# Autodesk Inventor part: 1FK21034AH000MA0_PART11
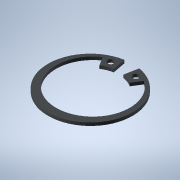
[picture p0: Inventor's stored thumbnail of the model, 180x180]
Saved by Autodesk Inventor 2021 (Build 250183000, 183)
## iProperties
Created: 2025-04
Part Number: 1FK21034AH000MA0_PART11
Material: Generic
Catalog Web Link: www.3dfindit.com
Description: -Servo synchronous motor
Document SubType Name: Modeling
Designer: psAdmin
Mass: 0.288797 g
Surface Area: 7.43416 cm^2
Volume: 0.288797 cm^3
Density: 1 g/cm^3
Appearance: PSOLRGB-212-217-219
Category: PARTsolutions
Title: 1FK21034AH000MA0_PART11
Author: Cadenas PARTsolutions
Comments: Servo synchronous motor
Sending System: PARTsolutions
Preprocessor: ST-DEVELOPER v19.3
PSOL_IDENT_0: {$CADENAS_DATA/23d-libs/siemens_ag/_cat_/ec/b7/1fk21034ah000ma0.prj},216 {VTYP=3D},{NB=1FK21034AH000
PSOL_IDENT_1: MA0_PART11},{LINA=1FK21034AH000MA0_PART11},{NN=1FK21034AH000MA0_PART11},{NOPRJ=TRUE},{DATE=19.08.202
PSOL_IDENT_2: 5 14:01:05},{GEOMDATE=30.07.2025 02:01:02},{VERSION=},{LINEID=10},{WBVAR=},{WBNUMERIC=}  {NB=1FK2103
PSOL_IDENT_3: 4AH000MA0_PART11},{LINA=1FK21034AH000MA0_PART11},{KT=DUMMY},{PREVIEW=../../../_pool_/7c/50/p_d211_xx
PSOL_IDENT_4: _00932j.png},{DESCSHORT=SIMOTICS S-1FK2 HD, SINAMICS S210 3AC 400V-480V, 1.01 Nm, 4500 rpm},{DESCLON
PSOL_IDENT_5: G=SIMOTICS S-1FK2 HD servo motor M0=1.27 Nm; PN = 0.48 kW at nN=4500 rpm (380-480 V); PN = 0.3 kW at
PSOL_IDENT_6: nN=2500 rpm (200-240 V); degree of protection IP64; cylindrical shaft D14 x 30 mm; absolute encoder
PSOL_IDENT_7: 22-bit + 12-bit multiturn (encoder AM22DQC); with OCC interface; plug size M17, rotatable; SIMOTICS
PSOL_IDENT_8: S-1FK2 servomotorfor a wide range of uses in industrial environments. SIMOTICS S‑1FK2 servomotors a
PSOL_IDENT_9: re compact synchronous motors with a high dynamic performance that set themselves apart as a result
PSOL_IDENT_10: of their high power density, degree of protection and overload capability. The motors are available
PSOL_IDENT_11: in two variants: as High Dynamic variant (highest dynamic performance as a result of the low intrins
PSOL_IDENT_12: ic moment of inertia for applications demanding a high dynamic performance with low moved masses) -
PSOL_IDENT_13: and as Compact variant (precise and stable closed-loop control for medium up to large moved masses a
PSOL_IDENT_14: s a result of a medium intrinsic moment of inertia). SIMOTICSS‑1FK2 servomotors fully exploit their
PSOL_IDENT_15: strengths in a system with the SINAMICSS210 frequency converter and simple connection using the one
PSOL_IDENT_16: cable connection (OCC). Advantages include the short control and positioning times, fast and precise
PSOL_IDENT_17: correction of disturbing quantities as well as stable control with a high dynamic performance. The
PSOL_IDENT_18: servo motors can be configured to address a wide range of requirements. For example with and without
PSOL_IDENT_19: holding brake, IP64 or IP65 degree of protection, singleturn or multiturn absolute encoders - to na
PSOL_IDENT_20: me just a few. Further, the servomotors are available in different shaft heights extending from 20 t
PSOL_IDENT_21: o 100. A shaft sealing ring is available to achieve an IP65 degree of protection and for subsequent
PSOL_IDENT_22: mounting at the motor or as spare part. SIMOTICS - the optimum motor for each and every motion contr
PSOL_IDENT_23: ol application.},{INTNO=4034106444822},{SUPPLIERALTNO=1FK2103-4AH00-0MA0},{MANUID=1FK21034AH000MA0},
PSOL_IDENT_24: {MANUNAME=Siemens},{MANUTYPEDESC=SYNCHRONOUS MOTOR 1FK2 HD 1,27 NM},{AAU732=SIMOTICS},{AAO057=S-1FK2
PSOL_IDENT_25: },{AAU734=SIMOTICS S-1FK2 HD servo motor M0=1.27 Nm; PN = 0.48 kW at nN=4500 rpm (380-480 V); PN = 0
PSOL_IDENT_26: .3 kW at nN=2500 rpm (200-240 V); degree of protection IP64; cylindrical shaft D14 x 30 mm; absolute
PSOL_IDENT_27: encoder 22-bit + 12-bit multiturn (encoder AM22DQC); with OCC interface; plug size M17, rotatable;}
PSOL_IDENT_28: ,{AAW338=SYNCHRONOUS MOTOR 1FK2 HD 1,27 NM},{AAO742=SIMOTICS},{AAO663=4034106444822},{NOCUPEROU=1},{
PSOL_IDENT_29: PRICEQUANTITY=1},{QUANTITYMIN=1},{QUANTITYINT=1},{CTN=85015100},{COO=RO},{AAO676=1FK2103-4AH00-0MA0}
PSOL_IDENT_30: ,{AAO677=Siemens AG},{ORDERUNIT=C62},{CONTENTUNIT=C62}
NB: 1FK21034AH000MA0_PART11
NT: Servo synchronous motor
NBSYN: $MANUID._PART11
LINA: 1FK21034AH000MA0_PART11
CATALOG: SIEMENS
PREVIEW: ../../../_pool_/7c/50/p_d211_xx_00932j.png
DESCSHORT: SIMOTICS S-1FK2 HD, SINAMICS S210 3AC 400V-480V, 1.01 Nm, 4500 rpm
DESCLONG: SIMOTICS S-1FK2 HD servo motor M0=1.27 Nm; PN = 0.48 kW at nN=4500 rpm (380-480 V); PN = 0.3 kW at nN=2500 rpm (200-240 V); degree of protection IP64; cylindric
INTNO: 4034106444822
SUPPLIERALTNO: 1FK2103-4AH00-0MA0
MANUID: 1FK21034AH000MA0
MANUNAME: Siemens
MANUTYPEDESC: SYNCHRONOUS MOTOR 1FK2 HD 1,27 NM
AAU732: SIMOTICS
AAO057: S-1FK2
AAU734: SIMOTICS S-1FK2 HD servo motor M0=1.27 Nm; PN = 0.48 kW at nN=4500 rpm (380-480 V); PN = 0.3 kW at nN=2500 rpm (200-240 V); degree of protection IP64; cylindric
AAW338: SYNCHRONOUS MOTOR 1FK2 HD 1,27 NM
AAO742: SIMOTICS
AAO663: 4034106444822.0
NOCUPEROU: 1
PRICEQUANTITY: 1
QUANTITYMIN: 1
QUANTITYINT: 1
CTN: 85015100
COO: RO
ARTICLENO: 1FK21034AH000MA0_PART11
BOMINFO: 1FK21034AH000MA0_PART11
CREATOR: CADENAS GmbH
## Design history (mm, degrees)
feature "2025_04_17_15_01_37_0314"
body "Solid1"
